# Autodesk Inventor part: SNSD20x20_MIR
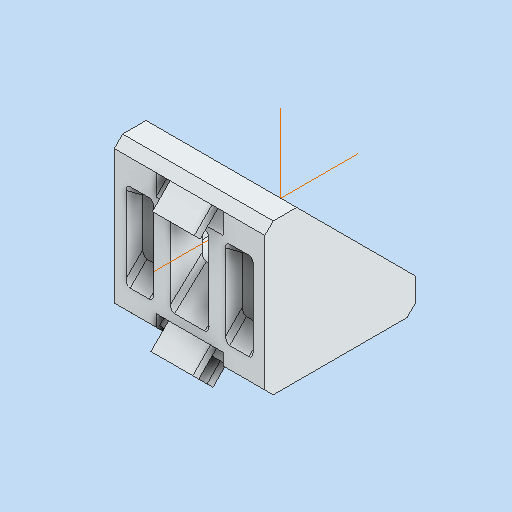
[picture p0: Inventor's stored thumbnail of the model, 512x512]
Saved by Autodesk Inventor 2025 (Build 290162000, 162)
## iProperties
Created: 2015-01
Part Number: SNSD20x20_MIR
Material: Типовые
Description: STEP AP214
Document SubType Name: Modeling
Designer: R5800u
Density: 1 g/cm^3
Appearance: Default
Company: XTreme.ws
Title: SNSD.30.52.29. Óãëîâîé àëþìèíèåâûé ñîåäèíèòåëü 20õ20, ïàç 6(H23).STEP
Author: XTreme.ws
Revision Number: ANY
Sending System: SolidWorks 2014
Preprocessor: SwSTEP 2.0
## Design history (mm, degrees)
derived "SNSD20x20.ipt"
  node "РабПлоскость1"
  node "РабПлоскость2"
  node "РабПлоскость3"
  node "РабПлоскость4"
  node "РабОсь1"
  node "РабОсь2"
feature "Твердое тело1::SNSD20x20.ipt"
tag "Lavorazione contrassegno1"
node "Твердое тело1"
